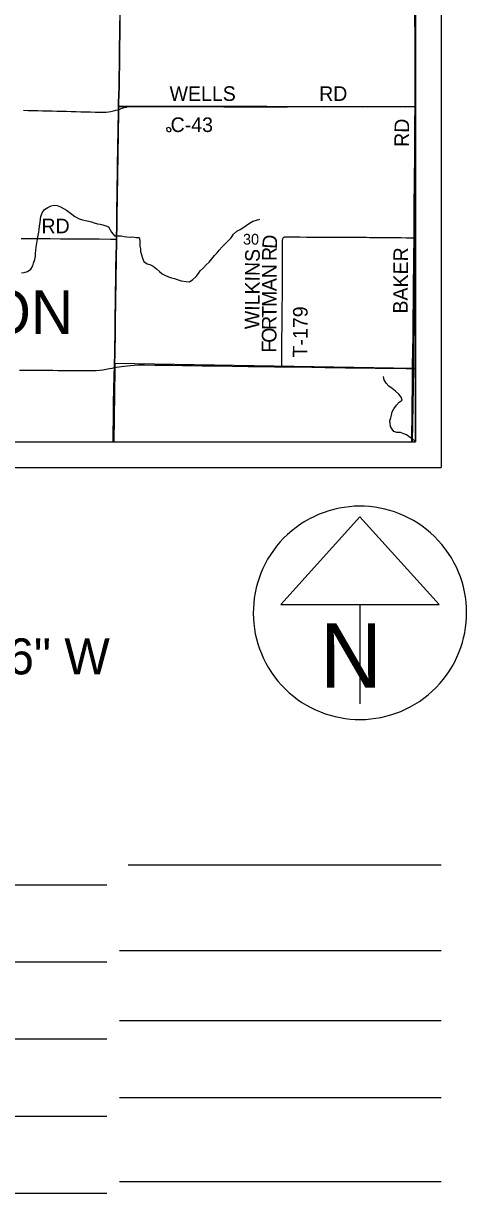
# Model space of a CAD drawing. Extents: x 0 to 34, y 0 to 22.
# Drawn here: x 7.376 to 9.099, y 11.177 to 15.728 of the extents above; entities that cross this region are included whole.
import ezdxf

# ---------------------------------------------------------------- set-up
doc = ezdxf.new("R2010")
doc.units = 0
for name, color, linetype in [('GM_X_Corporation', 7, 'Continuous'), ('GM_X_County_Road', 7, 'Continuous'), ('GM_X_County_Road_Text', 7, 'Continuous'), ('GM_X_Minor_Lake', 7, 'Continuous'), ('GM_X_Minor_River', 7, 'Continuous'), ('GM_X_Section_Text', 7, 'Continuous'), ('GM_X_State_Route', 7, 'Continuous'), ('GM_X_Township_Road', 7, 'Continuous'), ('GM_X_Township_Road_Text', 7, 'Continuous'), ('GM_X_Township_Text', 7, 'Continuous'), ('SH_Data', 7, 'Continuous'), ('SH_Text', 7, 'Continuous')]:
    doc.layers.add(name, color=color, linetype=linetype)

msp = doc.modelspace()

# ---------------------------------------------------------------- linework, layer by layer
at = {"layer": 'GM_X_Corporation'}
for points in [[(7.751, 15.7381), (7.7505, 15.7051), (7.7503, 15.6765), (7.7499, 15.6467), (7.7497, 15.6349), (7.7492, 15.5871), (7.7489, 15.5728), (7.7482, 15.5131), (7.748, 15.4939), (7.7477, 15.4771), (7.7472, 15.4541), (7.7462, 15.4168), (7.7459, 15.4045), (7.7457, 15.3926), (7.7453, 15.364), (7.7448, 15.3385), (7.7443, 15.3106), (7.7434, 15.2478), (7.742, 15.1714), (7.7413, 15.1329), (7.7407, 15.1006), (7.7404, 15.0801), (7.7402, 15.0614), (7.7397, 15.0055), (7.7394, 14.9732), (7.7386, 14.9328), (7.7381, 14.9042), (7.7379, 14.8877), (7.7377, 14.8713), (7.7364, 14.8204), (7.7359, 14.7825), (7.735, 14.7334), (7.734, 14.6775), (7.7336, 14.6402), (7.733, 14.593), (7.7325, 14.5557), (7.7322, 14.5097), (7.7316, 14.4612), (7.7309, 14.4289), (7.7307, 14.4184), (7.7307, 14.4153), (7.7304, 14.3991), (7.7301, 14.391), (7.73, 14.3894), (7.7295, 14.381), (7.7288, 14.3569), (7.7275, 14.3041), (7.7265, 14.2532), (7.7262, 14.2215), (7.7257, 14.1817), (7.725, 14.1395), (7.7245, 14.1071), (7.7244, 14.1), (8.9, 14.1), (8.9, 20.4201)], [(7.751, 15.7381), (7.7505, 15.7051), (7.7503, 15.6765), (7.7499, 15.6467), (7.7497, 15.6349), (7.7492, 15.5871), (7.7489, 15.5728), (7.7482, 15.5131), (7.748, 15.4939), (7.7477, 15.4771), (7.7472, 15.4541), (7.7462, 15.4168), (7.7459, 15.4045), (7.7457, 15.3926), (7.7453, 15.364), (7.7448, 15.3385), (7.7443, 15.3106), (7.7434, 15.2478), (7.742, 15.1714), (7.7413, 15.1329), (7.7407, 15.1006), (7.7404, 15.0801), (7.7402, 15.0614), (7.7397, 15.0055), (7.7394, 14.9732), (7.7386, 14.9328), (7.7381, 14.9042), (7.7379, 14.8877), (7.7377, 14.8713), (7.7364, 14.8204), (7.7359, 14.7825), (7.735, 14.7334), (7.734, 14.6775), (7.7336, 14.6402), (7.733, 14.593), (7.7325, 14.5557), (7.7322, 14.5097), (7.7316, 14.4612), (7.7309, 14.4289), (7.7307, 14.4184), (7.7307, 14.4153), (7.7304, 14.3991), (7.7301, 14.391), (7.73, 14.3894), (7.7295, 14.381), (7.7288, 14.3569), (7.7275, 14.3041), (7.7265, 14.2532), (7.7262, 14.2215), (7.7257, 14.1817), (7.725, 14.1395), (7.7245, 14.1071), (7.7244, 14.1), (8.9, 14.1), (8.9, 16.4207)], [(2.1, 14.1), (7.7244, 14.1), (7.7245, 14.1071), (7.725, 14.1395), (7.7257, 14.1817), (7.7262, 14.2215), (7.7265, 14.2532), (7.7275, 14.3041), (7.7288, 14.3569), (7.7295, 14.381), (7.73, 14.3894), (7.7301, 14.391), (7.7304, 14.3991), (7.7307, 14.4153), (7.7307, 14.4184), (7.7309, 14.4289), (7.7316, 14.4612), (7.7322, 14.5097), (7.7325, 14.5557), (7.733, 14.593), (7.7336, 14.6402), (7.734, 14.6775), (7.735, 14.7334), (7.7359, 14.7825), (7.7364, 14.8204), (7.7377, 14.8713), (7.7379, 14.8877), (7.7381, 14.9042), (7.7386, 14.9328), (7.7394, 14.9732), (7.7397, 15.0055), (7.7402, 15.0614), (7.7404, 15.0801), (7.7407, 15.1006), (7.7413, 15.1329), (7.742, 15.1714), (7.7434, 15.2478), (7.7443, 15.3106), (7.7448, 15.3385), (7.7453, 15.364), (7.7457, 15.3926), (7.7459, 15.4045), (7.7462, 15.4168), (7.7472, 15.4541), (7.7477, 15.4771), (7.748, 15.4939), (7.7482, 15.5131), (7.7489, 15.5728), (7.7492, 15.5871), (7.7497, 15.6349), (7.7499, 15.6467), (7.7503, 15.6765), (7.7505, 15.7051), (7.751, 15.7381)], [(2.1, 14.1), (7.7244, 14.1), (7.7245, 14.1071), (7.725, 14.1395), (7.7257, 14.1817), (7.7262, 14.2215), (7.7265, 14.2532), (7.7275, 14.3041), (7.7288, 14.3569), (7.7295, 14.381), (7.73, 14.3894), (7.7301, 14.391), (7.7304, 14.3991), (7.7307, 14.4153), (7.7307, 14.4184), (7.7309, 14.4289), (7.7316, 14.4612), (7.7322, 14.5097), (7.7325, 14.5557), (7.733, 14.593), (7.7336, 14.6402), (7.734, 14.6775), (7.735, 14.7334), (7.7359, 14.7825), (7.7364, 14.8204), (7.7377, 14.8713), (7.7379, 14.8877), (7.7381, 14.9042), (7.7386, 14.9328), (7.7394, 14.9732), (7.7397, 15.0055), (7.7402, 15.0614), (7.7404, 15.0801), (7.7407, 15.1006), (7.7413, 15.1329), (7.742, 15.1714), (7.7434, 15.2478), (7.7443, 15.3106), (7.7448, 15.3385), (7.7453, 15.364), (7.7457, 15.3926), (7.7459, 15.4045), (7.7462, 15.4168), (7.7472, 15.4541), (7.7477, 15.4771), (7.748, 15.4939), (7.7482, 15.5131), (7.7489, 15.5728), (7.7492, 15.5871), (7.7497, 15.6349), (7.7499, 15.6467), (7.7503, 15.6765), (7.7505, 15.7051), (7.751, 15.7381)]]:
    msp.add_lwpolyline(points, dxfattribs=at)
for points in [[(8.8965, 16.4176), (8.8984, 15.4027), (7.7473, 15.4057), (7.7624, 16.3866), (7.7629, 16.4174)], [(8.9, 15.4027), (8.9, 16.4176), (8.8965, 16.4176), (8.8984, 15.4027)], [(7.7473, 15.4057), (8.8984, 15.4027), (8.8924, 14.3857), (7.732, 14.4048), (7.7468, 15.3804)], [(8.9, 14.3857), (8.9, 15.4027), (8.8984, 15.4027), (8.8924, 14.3857)], [(7.7271, 14.1), (8.8882, 14.1), (8.8924, 14.3857), (7.732, 14.4048), (7.7316, 14.38)], [(8.8882, 14.1), (8.9, 14.1), (8.9, 14.3857), (8.8924, 14.3857)]]:
    msp.add_lwpolyline(points, close=True, dxfattribs=at)
at = {"layer": 'GM_X_County_Road'}
for p, q in [((7.7459, 15.3921), (7.7462, 15.4039)), ((8.8991, 15.4042), (8.9, 15.4042)), ((7.738, 14.8868), (7.738, 14.8888)), ((7.7298, 14.3804), (7.7302, 14.3889))]:
    msp.add_line(p, q, dxfattribs=at)
for points in [[(7.7462, 15.4039), (7.7464, 15.4163), (7.7474, 15.4535), (7.7477, 15.465), (7.7479, 15.4765), (7.7482, 15.4933), (7.7485, 15.5126), (7.7489, 15.5499), (7.749, 15.5611), (7.7491, 15.5722), (7.7494, 15.5865), (7.7498, 15.6198), (7.75, 15.6344), (7.7501, 15.6462), (7.7503, 15.6611), (7.7505, 15.676), (7.7508, 15.7046), (7.7512, 15.7375)], [(7.3758, 15.3899), (7.3944, 15.3894), (7.413, 15.389), (7.4317, 15.3885), (7.4503, 15.388), (7.4689, 15.3876), (7.4876, 15.3871), (7.5062, 15.3866), (7.5248, 15.3862), (7.5435, 15.3857), (7.5621, 15.3852), (7.5807, 15.3848), (7.5994, 15.3843), (7.618, 15.3838), (7.6367, 15.3833), (7.6553, 15.3829), (7.6669, 15.3826), (7.6785, 15.3823), (7.688, 15.3825), (7.6975, 15.3828), (7.707, 15.3838), (7.7164, 15.3852), (7.7258, 15.3871), (7.735, 15.3896), (7.7459, 15.3921)], [(7.738, 14.8888), (7.7383, 14.9037), (7.7386, 14.918), (7.7389, 14.9323), (7.7396, 14.9727), (7.7399, 15.005), (7.7401, 15.0236), (7.7403, 15.0423), (7.7404, 15.0516), (7.7406, 15.0795), (7.7407, 15.0898), (7.7409, 15.1), (7.7415, 15.1323), (7.7419, 15.151), (7.7421, 15.1609), (7.7422, 15.1709), (7.7432, 15.2268), (7.7436, 15.2473), (7.7442, 15.2846), (7.7446, 15.3101), (7.7448, 15.324), (7.745, 15.338), (7.7455, 15.3635), (7.7459, 15.3921)], [(7.7459, 15.3921), (7.7459, 15.3921), (7.7561, 15.3963), (7.7644, 15.3991), (7.7731, 15.4016), (7.7762, 15.4024)], [(7.7462, 15.4039), (7.75, 15.404), (7.7555, 15.404), (7.7646, 15.4041), (7.7707, 15.404), (7.7718, 15.4039), (7.7725, 15.4038), (7.7736, 15.4036), (7.7743, 15.4034), (7.7752, 15.4029), (7.7762, 15.4024)], [(7.7762, 15.4024), (7.7791, 15.4031), (7.7851, 15.404), (7.7937, 15.4045), (7.8384, 15.4042), (7.9136, 15.404), (7.9534, 15.404), (8.0199, 15.4039), (8.0498, 15.4039), (8.0926, 15.4039), (8.1299, 15.4041), (8.1554, 15.4038), (8.1939, 15.4037), (8.22, 15.4038), (8.2623, 15.4037), (8.3095, 15.4037), (8.3692, 15.4038), (8.4027, 15.4037), (8.4661, 15.4039), (8.4959, 15.4042), (8.5171, 15.4041), (8.5481, 15.4038), (8.6053, 15.404), (8.696, 15.4038), (8.8272, 15.4039), (8.8601, 15.4038), (8.8991, 15.4042)], [(7.7302, 14.3889), (7.7303, 14.3905), (7.7306, 14.3986), (7.7309, 14.4147), (7.7312, 14.4284), (7.7318, 14.4607), (7.732, 14.4793), (7.7324, 14.5092), (7.7325, 14.5278), (7.7327, 14.5551), (7.7332, 14.5924), (7.7335, 14.6111), (7.7337, 14.6254), (7.7339, 14.6396), (7.7341, 14.6676), (7.7342, 14.6769), (7.7353, 14.7328), (7.7356, 14.7515), (7.7359, 14.7667), (7.7361, 14.7819), (7.7364, 14.8006), (7.7365, 14.8102), (7.7366, 14.8198), (7.7371, 14.8385), (7.7375, 14.8546), (7.7379, 14.8708), (7.738, 14.8868)], [(7.7247, 14.1), (7.7248, 14.1066), (7.7252, 14.1389), (7.7255, 14.1576), (7.7257, 14.1694), (7.7259, 14.1812), (7.7262, 14.1998), (7.7263, 14.2104), (7.7264, 14.2209), (7.7267, 14.2526), (7.7271, 14.2713), (7.7278, 14.3036), (7.7282, 14.3222), (7.7286, 14.3393), (7.729, 14.3564), (7.7294, 14.3684), (7.7298, 14.3804)]]:
    msp.add_lwpolyline(points, dxfattribs=at)
at = {"layer": 'GM_X_Minor_Lake'}
msp.add_line((7.95, 15.3144), (7.947, 15.3205), dxfattribs=at)
for points in [[(7.947, 15.3205), (7.9417, 15.3229), (7.9329, 15.32), (7.9331, 15.3095)], [(7.9331, 15.3095), (7.9422, 15.3065), (7.9487, 15.3091), (7.95, 15.3144)]]:
    msp.add_lwpolyline(points, dxfattribs=at)
at = {"layer": 'GM_X_Minor_River'}
for points in [[(7.3684, 14.758), (7.3794, 14.7593), (7.3924, 14.7631), (7.4048, 14.7723), (7.412, 14.785), (7.4153, 14.7948), (7.4198, 14.8091), (7.4224, 14.8223), (7.4235, 14.8344), (7.4245, 14.8442), (7.4257, 14.8579), (7.4276, 14.8726), (7.4306, 14.8881), (7.4337, 14.9032), (7.4355, 14.9153), (7.4373, 14.9263), (7.4389, 14.941), (7.4407, 14.9539), (7.4426, 14.9671), (7.444, 14.9773), (7.4493, 14.9905), (7.4584, 15.0039), (7.4707, 15.0119), (7.4834, 15.0184), (7.4952, 15.0208)], [(7.4952, 15.0208), (7.5077, 15.0197), (7.5205, 15.0144), (7.5317, 15.0081), (7.5429, 15.0009), (7.5533, 14.9935), (7.5637, 14.9856), (7.5756, 14.9769), (7.5928, 14.9678), (7.6056, 14.9636), (7.6177, 14.961), (7.6301, 14.9581), (7.6403, 14.9555), (7.6512, 14.9522), (7.664, 14.9488), (7.6742, 14.9467), (7.6852, 14.9449), (7.6961, 14.9408), (7.7062, 14.9363), (7.7184, 14.9152), (7.7305, 14.9015), (7.7363, 14.9012)], [(7.7363, 14.9012), (7.7556, 14.9009), (7.7681, 14.8991), (7.7776, 14.8982), (7.7906, 14.8968), (7.8009, 14.897), (7.8135, 14.8952), (7.8257, 14.8954), (7.8281, 14.8839), (7.8283, 14.8717), (7.8292, 14.8618), (7.8306, 14.8504), (7.8315, 14.8405), (7.8351, 14.8271), (7.839, 14.8145), (7.8441, 14.8015), (7.8577, 14.7928), (7.8676, 14.7896), (7.88, 14.7833), (7.8928, 14.7728), (7.9052, 14.7623), (7.9157, 14.7537), (7.9263, 14.7482), (7.9407, 14.7422), (7.9521, 14.7386), (7.9639, 14.7353), (7.9741, 14.7321), (7.9897, 14.7268), (8.0087, 14.7242), (8.0216, 14.7228), (8.0348, 14.7321), (8.0476, 14.7436), (8.0566, 14.7556), (8.0633, 14.7658), (8.0757, 14.7773), (8.0862, 14.7893), (8.0979, 14.7997), (8.1088, 14.8121), (8.1194, 14.8252), (8.1295, 14.8356), (8.1377, 14.8461), (8.1482, 14.8592), (8.1607, 14.8704), (8.1727, 14.882), (8.1832, 14.8943), (8.1931, 14.9086), (8.2055, 14.9198), (8.2186, 14.9267), (8.2325, 14.9349), (8.2421, 14.9411), (8.2549, 14.9512), (8.2684, 14.9589), (8.2822, 14.9628), (8.2956, 14.966)], [(8.9, 14.1029), (8.8916, 14.1078), (8.8795, 14.1168), (8.866, 14.128), (8.8554, 14.1313), (8.8417, 14.1365), (8.8284, 14.1367), (8.8162, 14.14), (8.8099, 14.15), (8.8036, 14.1596), (8.802, 14.1725), (8.801, 14.1821), (8.8043, 14.1942), (8.8068, 14.2044), (8.8101, 14.2173), (8.8164, 14.2293), (8.8262, 14.2424), (8.8375, 14.254), (8.8494, 14.2618), (8.8443, 14.2737), (8.8354, 14.286), (8.8234, 14.2972), (8.8102, 14.3078), (8.797, 14.3167), (8.787, 14.3287), (8.7792, 14.3418), (8.7768, 14.354)]]:
    msp.add_lwpolyline(points, dxfattribs=at)
at = {"layer": 'GM_X_State_Route'}
for points in [[(7.3601, 14.3795), (7.3788, 14.3794), (7.3974, 14.3792), (7.4161, 14.3791), (7.4347, 14.379), (7.4533, 14.3788), (7.472, 14.3787), (7.4906, 14.3785), (7.5093, 14.3784), (7.5279, 14.3783), (7.5465, 14.3781), (7.5652, 14.378), (7.5838, 14.3779), (7.6025, 14.3777), (7.6177, 14.3776), (7.6329, 14.3775), (7.6459, 14.3776), (7.659, 14.3782), (7.672, 14.3793), (7.685, 14.3809), (7.6979, 14.3829), (7.7107, 14.3854), (7.7205, 14.3871), (7.7302, 14.3889)], [(7.7302, 14.3889), (7.7381, 14.3902), (7.7677, 14.3949), (7.7788, 14.3964), (7.7924, 14.3978), (7.8067, 14.3987), (7.8229, 14.3992), (7.8471, 14.3994), (7.8863, 14.3991), (7.9571, 14.398), (7.995, 14.3975), (8.0366, 14.397), (8.0714, 14.3965), (8.1466, 14.3953), (8.1876, 14.3947), (8.2498, 14.3936), (8.2957, 14.3928), (8.3517, 14.3921), (8.3807, 14.3917), (8.4977, 14.3903), (8.5493, 14.3898), (8.5803, 14.3892), (8.6282, 14.3884), (8.6729, 14.3879), (8.7443, 14.3871), (8.7804, 14.3869), (8.8282, 14.3863), (8.8643, 14.3858), (8.8895, 14.3856), (8.8928, 14.3856), (8.9, 14.3856)]]:
    msp.add_lwpolyline(points, dxfattribs=at)
at = {"layer": 'GM_X_Township_Road'}
for p, q in [((7.7459, 15.3921), (7.7462, 15.4039)), ((7.738, 14.8868), (7.738, 14.8888)), ((7.7298, 14.3804), (7.7302, 14.3889))]:
    msp.add_line(p, q, dxfattribs=at)
for points in [[(8.8991, 15.4042), (8.8993, 15.4231), (8.8994, 15.443), (8.8992, 15.466), (8.8993, 15.4858), (8.8993, 15.4989), (8.8992, 15.5244), (8.8992, 15.5486), (8.899, 15.5834), (8.8989, 15.6126), (8.8989, 15.6288), (8.8988, 15.6505), (8.8988, 15.6692), (8.8987, 15.6953), (8.8984, 15.7325), (8.8983, 15.7599), (8.8982, 15.8015), (8.898, 15.8214), (8.898, 15.8599), (8.898, 15.8742), (8.8979, 15.8866), (8.8981, 15.9123)], [(7.7462, 15.4039), (7.7464, 15.4163), (7.7474, 15.4535), (7.7477, 15.465), (7.7479, 15.4765), (7.7482, 15.4933), (7.7485, 15.5126), (7.7489, 15.5499), (7.749, 15.5611), (7.7491, 15.5722), (7.7494, 15.5865), (7.7498, 15.6198), (7.75, 15.6344), (7.7501, 15.6462), (7.7503, 15.6611), (7.7505, 15.676), (7.7508, 15.7046), (7.7512, 15.7375)], [(7.738, 14.8888), (7.7383, 14.9037), (7.7386, 14.918), (7.7389, 14.9323), (7.7396, 14.9727), (7.7399, 15.005), (7.7401, 15.0236), (7.7403, 15.0423), (7.7404, 15.0516), (7.7406, 15.0795), (7.7407, 15.0898), (7.7409, 15.1), (7.7415, 15.1323), (7.7419, 15.151), (7.7421, 15.1609), (7.7422, 15.1709), (7.7432, 15.2268), (7.7436, 15.2473), (7.7442, 15.2846), (7.7446, 15.3101), (7.7448, 15.324), (7.745, 15.338), (7.7455, 15.3635), (7.7459, 15.3921)], [(8.8949, 14.894), (8.8949, 14.9082), (8.8954, 14.9616), (8.8958, 15.0058), (8.896, 15.053), (8.8961, 15.0797), (8.8965, 15.1132), (8.8969, 15.1424), (8.8974, 15.1915), (8.8974, 15.2195), (8.8975, 15.2313), (8.8976, 15.2559), (8.8976, 15.2652), (8.898, 15.2863), (8.8982, 15.2987), (8.8984, 15.313), (8.8986, 15.3285), (8.8986, 15.3521), (8.8989, 15.385), (8.8991, 15.4017), (8.8991, 15.4042)], [(7.3665, 14.8915), (7.3851, 14.8912), (7.4037, 14.891), (7.4224, 14.8908), (7.4489, 14.8909), (7.4798, 14.8909), (7.5197, 14.8903), (7.5683, 14.8903), (7.6223, 14.8902), (7.6706, 14.8895), (7.7139, 14.889), (7.738, 14.8888)], [(7.7302, 14.3889), (7.7303, 14.3905), (7.7306, 14.3986), (7.7309, 14.4147), (7.7312, 14.4284), (7.7318, 14.4607), (7.732, 14.4793), (7.7324, 14.5092), (7.7325, 14.5278), (7.7327, 14.5551), (7.7332, 14.5924), (7.7335, 14.6111), (7.7337, 14.6254), (7.7339, 14.6396), (7.7341, 14.6676), (7.7342, 14.6769), (7.7353, 14.7328), (7.7356, 14.7515), (7.7359, 14.7667), (7.7361, 14.7819), (7.7364, 14.8006), (7.7365, 14.8102), (7.7366, 14.8198), (7.7371, 14.8385), (7.7375, 14.8546), (7.7379, 14.8708), (7.738, 14.8868)], [(8.3807, 14.3917), (8.3807, 14.3986), (8.3807, 14.3999), (8.3807, 14.4179), (8.3809, 14.4446), (8.3813, 14.4912), (8.3819, 14.5596), (8.3823, 14.5838), (8.3825, 14.6105), (8.3825, 14.6205), (8.3825, 14.6273), (8.3828, 14.6658), (8.3828, 14.6751), (8.3829, 14.6957), (8.3829, 14.7062), (8.383, 14.7124), (8.3832, 14.7485), (8.3833, 14.7677), (8.3833, 14.7802), (8.3833, 14.7901), (8.3834, 14.7994), (8.3834, 14.8075), (8.3835, 14.8149), (8.3835, 14.8236), (8.3836, 14.8317), (8.3836, 14.8391), (8.3836, 14.8522), (8.3836, 14.8603), (8.3835, 14.8659), (8.3835, 14.8739), (8.3835, 14.882), (8.3837, 14.8857), (8.3841, 14.8888), (8.3848, 14.8912), (8.3859, 14.8934), (8.3871, 14.8948), (8.3891, 14.8963), (8.3902, 14.8968), (8.3926, 14.8975), (8.3944, 14.8978), (8.3987, 14.8981), (8.4037, 14.898), (8.4143, 14.8977), (8.4329, 14.8973), (8.4509, 14.8971), (8.4764, 14.8969), (8.4919, 14.8968), (8.546, 14.8967), (8.5572, 14.8965), (8.5901, 14.8962), (8.5988, 14.8962), (8.6249, 14.896), (8.6379, 14.8959), (8.6622, 14.8958), (8.6746, 14.8957), (8.6988, 14.8957), (8.7106, 14.8957), (8.7218, 14.8956), (8.7417, 14.8954), (8.7498, 14.8954), (8.7771, 14.8951), (8.7864, 14.895), (8.8026, 14.8948), (8.8206, 14.8947), (8.8349, 14.8946), (8.8455, 14.8945), (8.8647, 14.8943), (8.8765, 14.8941), (8.8903, 14.894), (8.8949, 14.894)], [(8.8895, 14.3856), (8.8895, 14.3909), (8.8895, 14.4006), (8.8902, 14.4509), (8.8912, 14.5162), (8.8915, 14.5354), (8.8917, 14.5559), (8.8921, 14.5994), (8.8925, 14.6336), (8.8925, 14.6417), (8.8927, 14.6615), (8.8928, 14.6758), (8.8931, 14.7106), (8.8935, 14.7429), (8.8938, 14.7609), (8.894, 14.774), (8.8942, 14.7976), (8.8945, 14.8386), (8.8948, 14.8703), (8.8948, 14.8889), (8.8949, 14.894)], [(8.8865, 14.1), (8.8866, 14.1149), (8.8867, 14.1286), (8.8869, 14.141), (8.887, 14.1571), (8.8872, 14.172), (8.8873, 14.1807), (8.8875, 14.2), (8.8878, 14.2242), (8.8881, 14.2342), (8.8883, 14.2615), (8.8883, 14.2708), (8.8886, 14.2894), (8.8888, 14.305), (8.889, 14.3217), (8.8892, 14.3366), (8.8893, 14.3509), (8.8894, 14.3596), (8.8895, 14.3708), (8.8895, 14.3856)], [(7.7247, 14.1), (7.7248, 14.1066), (7.7252, 14.1389), (7.7255, 14.1576), (7.7257, 14.1694), (7.7259, 14.1812), (7.7262, 14.1998), (7.7263, 14.2104), (7.7264, 14.2209), (7.7267, 14.2526), (7.7271, 14.2713), (7.7278, 14.3036), (7.7282, 14.3222), (7.7286, 14.3393), (7.729, 14.3564), (7.7294, 14.3684), (7.7298, 14.3804)]]:
    msp.add_lwpolyline(points, dxfattribs=at)
at = {"layer": 'SH_Data'}
for p, q in [((9, 21), (9, 14)), ((8.9, 20.9), (8.9, 14.1)), ((8.9, 20.9), (8.9, 14.1)), ((2.1, 14.1), (8.9, 14.1)), ((2.1, 14.1), (8.9, 14.1)), ((2, 14), (9, 14)), ((8.6845, 13.8091), (8.3769, 13.4678)), ((8.9921, 13.4678), (8.6845, 13.8091)), ((8.3769, 13.4678), (8.9921, 13.4678)), ((8.6845, 13.4678), (8.6845, 13.0811)), ((8.6845, 13.4353), (8.6845, 13.4353)), ((8.6845, 13.4353), (8.6845, 13.4353)), ((7.7827, 12.4553), (9, 12.4553)), ((7.7, 12.3767), (4.4937, 12.3767)), ((9, 12.1207), (7.75, 12.1207)), ((7.7, 12.0767), (3.9895, 12.0767)), ((9, 11.8491), (7.75, 11.8491)), ((7.7, 11.7767), (3.6192, 11.7767)), ((9, 11.5491), (7.75, 11.5491)), ((7.7, 11.4767), (3.3288, 11.4767)), ((9, 11.2223), (7.75, 11.2223)), ((7.7, 11.1767), (4.7452, 11.1767))]:
    msp.add_line(p, q, dxfattribs=at)
msp.add_arc((8.6845, 13.4353), 0.4148, 129.7798, 129.7633, dxfattribs=at)

# ---------------------------------------------------------------- texts
at = {"layer": 'GM_X_County_Road_Text'}
for s, p in [('WELLS', (7.9442, 15.4263)), ('RD', (8.5258, 15.4263)), ('C-43', (7.9483, 15.3053))]:
    msp.add_text(s, height=0.05682, rotation=0, dxfattribs=at).set_placement(p)
at = {"layer": 'GM_X_Section_Text'}
msp.add_text('30', height=0.04186, rotation=0, dxfattribs=at).set_placement((8.23, 14.8674))
at = {"layer": 'GM_X_Township_Road_Text'}
for s, height, rotation, p in [('RD', 0.05682, 89.5084, (8.8752, 15.2472)), ('RD', 0.05682, 0, (7.446, 14.9114)), ('D', 0.0568, 86.4241, (8.361, 14.8495)), ('WILKINS', 0.05682, 89.6759, (8.2935, 14.5381)), ('R', 0.0568, 89.7775, (8.3609, 14.8037)), ('BAKER', 0.05682, 89.5941, (8.8701, 14.5991)), ('N', 0.0568, 89.7887, (8.3606, 14.7362)), ('A', 0.0568, 89.7887, (8.3604, 14.6862)), ('M', 0.0568, 89.7888, (8.3602, 14.6246)), ('T', 0.0568, 89.7857, (8.36, 14.5821)), ('T-179', 0.05682, 89.7187, (8.4803, 14.4285)), ('R', 0.0568, 89.7872, (8.3599, 14.5354)), ('O', 0.0568, 89.7887, (8.3597, 14.4854)), ('F', 0.0568, 89.7909, (8.3595, 14.4471))]:
    msp.add_text(s, height=height, rotation=rotation, dxfattribs=at).set_placement(p)
at = {"layer": 'GM_X_Township_Text'}
msp.add_text('JACKSON', height=0.17045, rotation=0, dxfattribs=at).set_placement((6.4931, 14.5195))
at = {"layer": 'SH_Data'}
msp.add_text('N', height=0.25, dxfattribs=at).set_placement((8.5292, 13.144))
at = {"layer": 'SH_Text'}
msp.add_text('LATITUDE:   40°26\'13" N    LONGITUDE:   84°22\'26" W', height=0.14, dxfattribs=at).set_placement((3.071, 13.1959))

doc.saveas('drawing.dxf')
